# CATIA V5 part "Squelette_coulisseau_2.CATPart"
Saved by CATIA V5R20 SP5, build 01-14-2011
Part number: Squelette_coulisseau_2
Publications: "Plan xy", "Plan yz", "Plan zx", "Longueur_coulisseau_2", "Largeur_coulisseau_2", "Point.1", "Point.2", "Point.3", "Point.4", "Droite.1", "Droite.2", "Droite.3", "Droite.4", "Point.5", "Droite.5"
Bounding box of the stored display mesh (mm): x 0 to 16, y 0 to 10, z 0 to 20
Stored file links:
  C:\Users\MARLENE\Documents\IFMA\S3\IAO\Copie de CAO\Squelette_coulisseau_2.CATPart
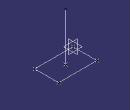
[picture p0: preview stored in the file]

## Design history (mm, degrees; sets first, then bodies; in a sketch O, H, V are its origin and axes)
Parameters
  Longueur_coulisseau_2 = 16 mm
  Largeur_coulisseau_2 = 10 mm
Set1
  Point1: (0, 0, 0)
  Point2: (16 {= Longueur_coulisseau_2}, 0, 0)
  Point3: (16 {= Longueur_coulisseau_2}, 10 {= Largeur_coulisseau_2}, 0)
  Point4: (0, 10 {= Largeur_coulisseau_2}, 0)
  Line1: type PtPt, FirstPoint Point1, SecondPoint Point4
  Line2: type PtPt, FirstPoint Point4, SecondPoint Point3
  Line3: type PtPt, FirstPoint Point3, SecondPoint Point2
  Line4: type PtPt, FirstPoint Point1, SecondPoint Point2
  Point5: (8 {= Longueur_coulisseau_2 /2}, 5 {= Largeur_coulisseau_2 /2}, 0)
  Line5: type PtDir, RefPoint Point5, Direction xy-plane, Start 0, End 20
Body1 (main body)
